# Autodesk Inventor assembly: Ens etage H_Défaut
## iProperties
Shininess: 64.0
Length Units: 11269
Angle Units: 11279
Time Units: 11290
Mass Units: 11283
Length Display Precision: 3
Angle Display Precision: 2
Compacted: True
Created: 2006-01
Part Number: Ens etage H_Défaut
Document SubType Name: Assembly
Designer: Fricot
Density: 0.0
Volumn: 0.0
Area: 0.0
PropertySet Name: Model Information
Control State: 0
Master: False
Checked Out: False
Author: Fricot
